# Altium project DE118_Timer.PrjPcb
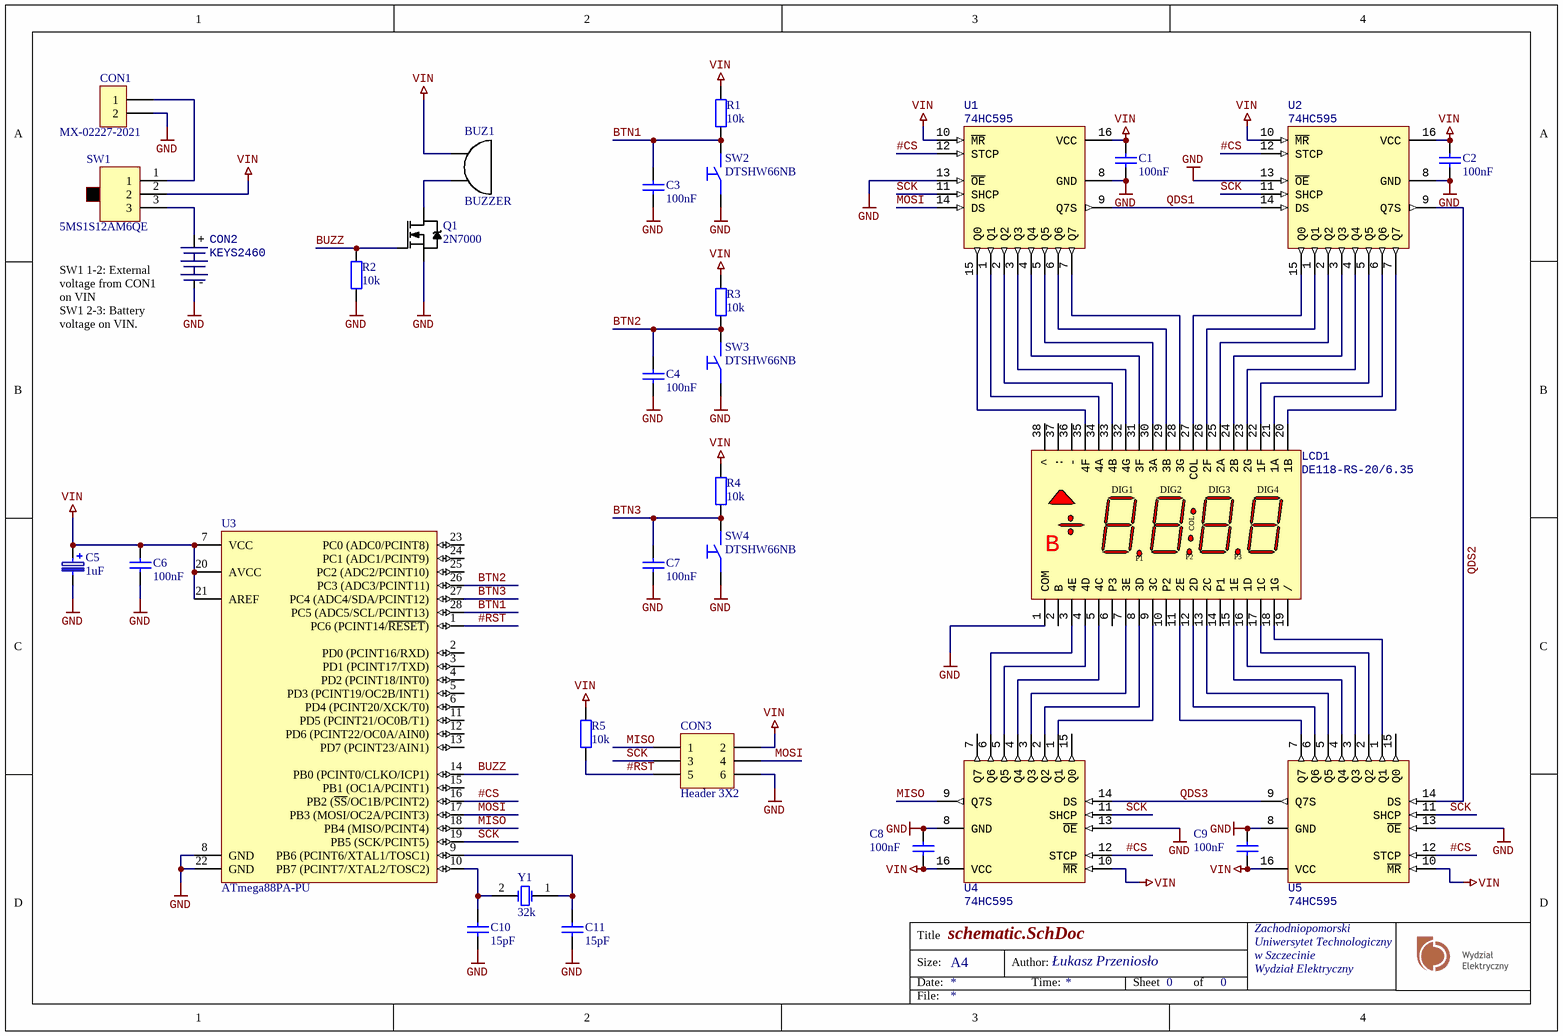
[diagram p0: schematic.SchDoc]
1 sheet, 32 parts. Net scope: global (net labels, ports and power ports of the same name join across sheets).
Board file: DE118_Timer.PcbDoc

## Sheet schematic.SchDoc: Test
size A4; DrawnBy: Łukasz Przeniosło; Organization: Zachodniopomorski; Address1: Uniwersytet Technologiczny; Address2: w Szczecinie; Address3: Wydział Elektryczny; DocumentNumber: 1111; Revision: 1.0; SheetNumber: 0; SheetTotal: 0

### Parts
BUZ1  BUZZER  [BUZZER-14mm]
C1  100nF  [CAP-5x2.5]
C2  100nF  [CAP-5x2.5]
C3  100nF  [CAP-5x2.5]
C4  100nF  [CAP-5x2.5]
C5  1uF  [CAPPR3.5-8x12]
C6  100nF  [CAP-5x2.5]
C7  100nF  [CAP-5x2.5]
C8  100nF  [CAP-5x2.5]
C9  100nF  [CAP-5x2.5]
C10  15pF  [CAP-5x2.5]
C11  15pF  [CAP-5x2.5]
CON1  MX-02227-2021  [MX-02227-2021]
CON2  KEYS2460  [BAT_HOLDER_2479RB]
CON3  Header 3X2  [HDR2X3_IDC]
LCD1  DE118-RS-20/6.35  [DE118]
Q1  2N7000  [TO92_WIDE]
R1  10k  [RES_AXIAL_0W25]
R2  10k  [RES_AXIAL_0W25]
R3  10k  [RES_AXIAL_0W25]
R4  10k  [RES_AXIAL_0W25]
R5  10k  [RES_AXIAL_0W25]
SW1  5MS1S12AM6QE  [5MS1S12AM6QE]
SW2  DTSHW66NB  [FSM2J]
SW3  DTSHW66NB  [FSM2J]
SW4  DTSHW66NB  [FSM2J]
U1  74HC595  [DIP16]
U2  74HC595  [DIP16]
U3  ATmega88PA-PU  [DIP28]
U4  74HC595  [DIP16]
U5  74HC595  [DIP16]
Y1  32k  [HC-49U]

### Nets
GND: C1.1 C2.1 C3.1 C4.1 C5.2 C6.1 C7.1 C8.1 C9.1 C10.1 C11.1 CON1.2 CON2.2(BAT-) CON3.6 LCD1.1(COM) Q1.3(S) R2.1 SW2.1 SW3.1 SW4.1 U1.8(GND) U1.13(~{OE}) U2.8(GND) U2.13(~{OE}) U3.8(GND) U3.22(GND) U4.8(GND) U4.13(~{OE}) U5.8(GND) U5.13(~{OE})
VIN: BUZ1.1 C1.2 C2.2 C5.1 C6.2 C8.2 C9.2 CON3.2 R1.2 R3.2 R4.2 R5.2 SW1.2 U1.10(~{MR}) U1.16(VCC) U2.10(~{MR}) U2.16(VCC) U3.7(VCC) U3.20(AVCC) U3.21(AREF) U4.10(~{MR}) U4.16(VCC) U5.10(~{MR}) U5.16(VCC)
#CS: U1.12(STCP) U2.12(STCP) U3.16(PB2_(~{SS}/OC1B/PCINT2)) U4.12(STCP) U5.12(STCP)
#RST: CON3.5 R5.1 U3.1(PC6_(PCINT14/~{RESET}))
BTN1: C3.2 R1.1 SW2.2 U3.28(PC5_(ADC5/SCL/PCINT13))
BTN2: C4.2 R3.1 SW3.2 U3.26(PC3_(ADC3/PCINT11))
BTN3: C7.2 R4.1 SW4.2 U3.27(PC4_(ADC4/SDA/PCINT12))
BUZZ: Q1.2(G) R2.2 U3.14(PB0_(PCINT0/CLKO/ICP1))
MISO: CON3.1 U3.18(PB4_(MISO/PCINT4)) U4.9(Q7S)
MOSI: CON3.4 U1.14(DS) U3.17(PB3_(MOSI/OC2A/PCINT3))
QDS1: U1.9(Q7S) U2.14(DS)
QDS2: U2.9(Q7S) U5.14(DS)
QDS3: U4.14(DS) U5.9(Q7S)
SCK: CON3.3 U1.11(SHCP) U2.11(SHCP) U3.19(PB5_(SCK/PCINT5)) U4.11(SHCP) U5.11(SHCP)
NetBUZ1_2: BUZ1.2 Q1.1(D)
NetC10_2: C10.2 U3.10(PB7_(PCINT7/XTAL2/TOSC2)) Y1.2(OSC2)
NetC11_2: C11.2 U3.9(PB6_(PCINT6/XTAL1/TOSC1)) Y1.1(OSC1)
NetCON1_1: CON1.1 SW1.1
NetCON2_1: CON2.1(BAT+) SW1.3
NetLCD1_3: LCD1.3(4E) U4.6(Q6)
NetLCD1_4: LCD1.4(4D) U4.5(Q5)
NetLCD1_5: LCD1.5(4C) U4.4(Q4)
NetLCD1_7: LCD1.7(3E) U4.3(Q3)
NetLCD1_8: LCD1.8(3D) U4.2(Q2)
NetLCD1_9: LCD1.9(3C) U4.1(Q1)
NetLCD1_11: LCD1.11(2E) U5.7(Q7)
NetLCD1_12: LCD1.12(2D) U5.6(Q6)
NetLCD1_13: LCD1.13(2C) U5.5(Q5)
NetLCD1_15: LCD1.15(1E) U5.4(Q4)
NetLCD1_16: LCD1.16(1D) U5.3(Q3)
NetLCD1_17: LCD1.17(1C) U5.2(Q2)
NetLCD1_18: LCD1.18(1G) U5.1(Q1)
NetLCD1_20: LCD1.20(1B) U2.7(Q7)
NetLCD1_21: LCD1.21(1A) U2.6(Q6)
NetLCD1_22: LCD1.22(1F) U2.5(Q5)
NetLCD1_23: LCD1.23(2G) U2.4(Q4)
NetLCD1_24: LCD1.24(2B) U2.3(Q3)
NetLCD1_25: LCD1.25(2A) U2.2(Q2)
NetLCD1_26: LCD1.26(2F) U2.1(Q1)
NetLCD1_27: LCD1.27(COL) U2.15(Q0)
NetLCD1_28: LCD1.28(3G) U1.7(Q7)
NetLCD1_29: LCD1.29(3B) U1.6(Q6)
NetLCD1_30: LCD1.30(3A) U1.5(Q5)
NetLCD1_31: LCD1.31(3F) U1.4(Q4)
NetLCD1_32: LCD1.32(4G) U1.3(Q3)
NetLCD1_33: LCD1.33(4B) U1.2(Q2)
NetLCD1_34: LCD1.34(4A) U1.1(Q1)
NetLCD1_35: LCD1.35(4F) U1.15(Q0)

Not connected (* = marked no-connect by the designer): LCD1 2(B) 6(P3) 10(P2) 14(P1) 19(/) 36(-) 37(:) 38(^); U3 2(PD0_(PCINT16/RXD)) 3(PD1_(PCINT17/TXD)) 4(PD2_(PCINT18/INT0)) 5(PD3_(PCINT19/OC2B/INT1)) 6(PD4_(PCINT20/XCK/T0)) 11(PD5_(PCINT21/OC0B/T1)) 12(PD6_(PCINT22/OC0A/AIN0)) 13(PD7_(PCINT23/AIN1)) 15(PB1_(OC1A/PCINT1)) 23(PC0_(ADC0/PCINT8)) 24(PC1_(ADC1/PCINT9)) 25(PC2_(ADC2/PCINT10)); U4 7(Q7) 15(Q0); U5 15(Q0)

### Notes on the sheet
- (near CON2) SW1 1-2: External voltage from CON1 on VIN
  SW1 2-3: Battery voltage on VIN.

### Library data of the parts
C1-C4 C6-C11 = Cap: Capacitor
C5 = Capacitor Tantalum
CON1 = MX-02227-2021: Pith 2.54mm, 2-pin
CON2 = KEYS2460: Holds Three (3) “AAA” Cells in Series
CON3 = Header 3X2: Header, 3-Pin, Dual row
LCD1 = DE118-RS-20/6.35: Wyświetlacz: LCD; cyfrowy; STN Positive; Il.cyfr:4; Znak:8mm
R1-R5 = Resistor: Tolerance: 5%; Power: 0W
SW2-SW4 = DTSHW66NB: SWITCH, SPNO TACT
U1 U2 U4 U5 = 74HC595: 8-bit serial-in, serial or parallel-out shift register with output latches; 3-state
U3 = ATmega88PA-PU: 8-bit AVR Microcontroller, 8KB Flash, 512 Bytes EEPROM, 1KB SRAM, 28-pin PDIP, Industrial Grade (-40°C to 85°C)
Y1 = XTAL: Crystal Oscillator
